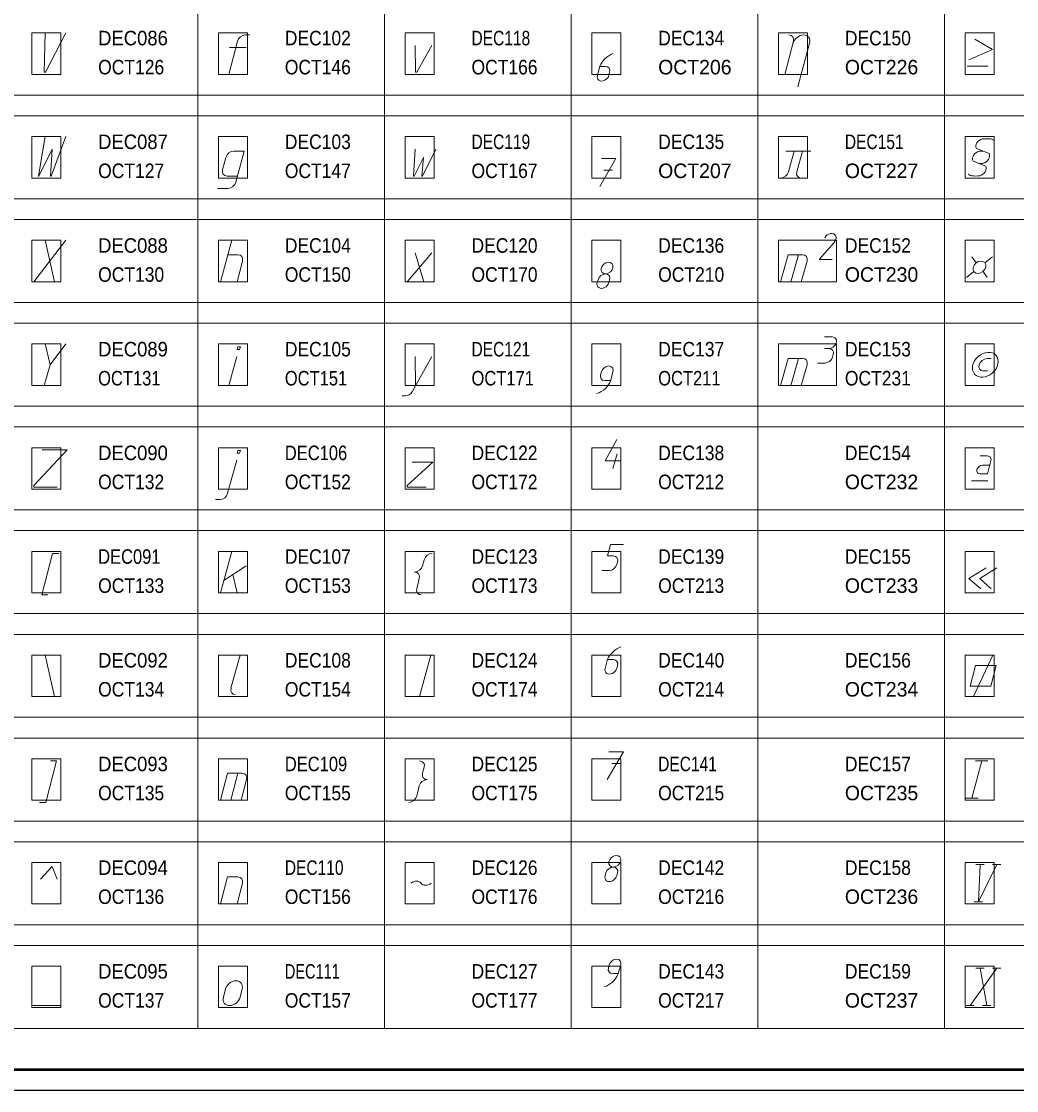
# Model space of a CAD drawing. Extents: x -200 to 7300, y -200 to 4800.
# Drawn here: x 2225 to 4624, y -200 to 2378 of the extents above; entities that cross this region are included whole.
import ezdxf

# ---------------------------------------------------------------- set-up
doc = ezdxf.new("R2010")
doc.units = 0
doc.header["$LTSCALE"] = 14
for name, color, linetype, lineweight in [('1', 7, 'Continuous', 13), ('5', 7, 'Continuous', 40), ('6', 7, 'Continuous', 13), ('63', 7, 'Continuous', 13)]:
    doc.layers.add(name, color=color, linetype=linetype, lineweight=lineweight)
doc.layers.add('10', color=7, linetype='Continuous')
doc.layers.add('11', color=7, linetype='Continuous')

msp = doc.modelspace()

# ---------------------------------------------------------------- linework, layer by layer
at = {"layer": '1'}
for p, q in [((2746, 2330), (2725, 2250)), ((2775, 2345), (2765, 2345)), ((4065, 2250), (4086, 2330)), ((4097, 2220), (4125, 2325)), ((2727, 2315), (2767, 2315)), ((3619, 2270), (3613.4, 2248)), ((3619, 2269), (3633, 2269)), ((4505, 2270), (4555, 2270)), ((3643, 2255), (3641.4, 2247.9)), ((4068, 2065), (4128, 2065)), ((4088, 2065), (4074, 2015)), ((4108, 2065), (4094, 2015)), ((4527, 2071), (4557.7, 2059)), ((2710, 2020), (2718, 2050)), ((4519, 2041), (4549.7, 2029)), ((3629, 2019), (3650, 2019)), ((2746, 2005), (2721, 2005)), ((2723, 1975), (2698, 1975)), ((2332, 1850), (2255, 1750)), ((2282, 1850), (2305, 1750)), ((2732, 1850), (2705, 1750)), ((2722, 1815), (2747, 1815)), ((3214, 1820), (3155, 1750)), ((3174, 1820), (3195, 1750)), ((4098, 1815), (4080, 1750)), ((4516, 1810), (4526.4, 1795.5)), ((4566, 1810), (4547.7, 1795.7)), ((2758, 1800), (2745, 1750)), ((4119, 1800), (4105, 1750)), ((3615, 1755), (3613, 1748)), ((3643, 1755), (3641, 1748)), ((4503, 1760), (4520.7, 1774.6)), ((4553, 1760), (4543, 1775)), ((4179, 1617), (4161, 1617)), ((4172, 1589), (4161, 1589)), ((4182, 1575), (4180, 1568)), ((2294, 1550), (2280, 1500)), ((2725, 1500), (2744, 1570)), ((3214, 1570), (3167, 1485)), ((3174, 1570), (3175, 1500)), ((4098, 1565), (4080, 1500)), ((4119, 1550), (4105, 1500)), ((4162, 1554), (4144, 1554)), ((4563, 1565), (4553, 1565)), ((3621, 1526), (3623, 1533)), ((3646, 1513), (3651, 1533)), ((4544, 1535), (4554, 1535)), ((3646, 1512), (3631, 1512)), ((3150, 1475), (3143, 1475)), ((2744, 1320), (2722, 1240)), ((3651, 1300), (3661, 1335)), ((4536, 1330), (4551.5, 1330)), ((4542, 1308), (4560, 1308)), ((4515, 1270), (4555, 1270)), ((2703, 1225), (2693, 1225)), ((2732, 1100), (2705, 1000)), ((2767, 1065), (2713, 1030)), ((3196, 1080), (3192, 1065)), ((3662, 1075), (3660, 1068)), ((2745, 1000), (2735, 1044)), ((3178, 1010), (3184, 1035)), ((3624, 1054), (3642, 1054)), ((2305, 750), (2282, 850)), ((2752, 850), (2730, 770)), ((3212, 850), (3185, 750)), ((3638, 840), (3632, 818)), ((3638, 839), (3652, 839)), ((3662, 825), (3660, 818)), ((4520, 750), (4567, 850)), ((4540, 595), (4516, 505)), ((4525, 595), (4555, 595)), ((3196, 580), (3192, 565)), ((3648, 589), (3669, 589)), ((2747, 565), (2730, 500)), ((2768, 550), (2755, 500)), ((3178, 510), (3184, 535)), ((4501, 505), (4531, 505)), ((4526, 345), (4546, 345)), ((4586, 345), (4566, 345)), ((3634, 325), (3632, 318)), ((3662, 325), (3660, 318)), ((2758, 300), (2745, 250)), ((4522, 255), (4542, 255)), ((3640, 96), (3642, 103)), ((3664, 82), (3650, 82)), ((3663, 80), (3670, 103)), ((4576, 95), (4512, 5)), ((4526, 95), (4546, 95)), ((4536, 95), (4552, 5)), ((4586, 95), (4566, 95)), ((2717, 45), (2712, 25)), ((2757, 45), (2752, 25)), ((2251, 5), (2321, 5)), ((4502, 5), (4522, 5)), ((4542, 5), (4562, 5))]:
    msp.add_line(p, q, dxfattribs=at)
for points in [[(2282, 2350), (2280, 2255), (2283, 2255), (2332, 2350)], [(3174, 2320), (3175, 2255), (3178, 2255), (3214, 2320)], [(4523, 2335), (4566, 2310), (4509, 2285)], [(2282, 2100), (2266, 2005), (2267, 2005), (2299, 2070), (2295, 2005), (2297, 2005), (2332, 2100)], [(2737, 2065), (2762, 2065), (2742, 1990)], [(3174, 2070), (3170, 2005), (3172, 2005), (3194, 2050), (3190, 2005), (3192, 2005), (3224, 2070)], [(3623, 2047), (3658, 2047), (3619, 1980)], [(4179, 1804), (4148, 1804), (4184, 1845)], [(4055, 1750), (4073, 1815), (4108, 1815)], [(2282, 1600), (2294, 1550), (2332, 1600)], [(4055, 1500), (4073, 1565), (4108, 1565)], [(3670, 1318), (3632, 1318), (3660, 1370)], [(2275, 1345), (2335, 1345), (2255, 1259), (2255, 1255), (2311, 1255)], [(3167, 1315), (3217, 1315), (3155, 1259), (3155, 1255), (3201, 1255)], [(4562, 1319), (4554, 1287), (4536, 1287)], [(3676, 1117), (3645, 1117), (3638, 1089), (3652, 1089)], [(2315, 1095), (2300, 1095), (2274, 995), (2289, 995)], [(4551, 1060), (4509, 1035), (4538, 1010)], [(4576, 1060), (4535, 1035), (4563, 1010)], [(2295, 595), (2310, 595), (2284, 495), (2269, 495)], [(3641, 617), (3676, 617), (3637, 550)], [(2705, 500), (2722, 565), (2757, 565)], [(2311, 310), (2299, 340), (2271, 310)], [(4536, 345), (4532, 255), (4576, 345)], [(2705, 250), (2722, 315), (2747, 315)]]:
    msp.add_lwpolyline(points, dxfattribs=at)
for points in [[(2745, 1587), (2751, 1587), (2753, 1593), (2747, 1593)], [(2745, 1337), (2751, 1337), (2753, 1343), (2747, 1343)], [(4512, 775), (4562, 775), (4575, 825), (4525, 825)]]:
    msp.add_lwpolyline(points, close=True, dxfattribs=at)
for centre, major_axis, ratio, start_param, end_param in [((2761, 2330), (-12.9, -11.29), 0.765566, 3.860429, 5.4312252), ((4071, 2330), (-12.9, -11.29), 0.765566, 2.2896327, 3.860429), ((4105, 2325), (-17.2, -15.05), 0.765566, 2.2896327, 5.4312253), ((3657.28, 2262.33), (-35.31, -30.9), 0.765566, 4.2695852, 5.2433836), ((3629, 2255), (-12.04, -10.54), 0.765566, 2.2896326, 3.8604289), ((3627.39, 2247.96), (-12.04, -10.54), 0.765566, 5.4286742, 8.5753689), ((4541.35, 2080), (-12.9, -11.29), 0.765566, 4.1387286, 6.0747263), ((4549.03, 2090), (-20.04, -0.36), 0.248806, 3.0702852, 5.1041698), ((2732.98, 2050), (-12.9, -11.29), 0.765566, 3.860429, 5.4312252), ((4533.32, 2050), (-12.9, -11.29), 0.765566, 4.1387286, 6.0747263), ((4541, 2060), (-20.04, -0.36), 0.248806, 4.6410815, 5.1041696), ((4543.32, 2050), (-12.9, -11.29), 0.765566, 0.9971359, 2.9331337), ((2725.02, 2020), (12.9, 11.29), 0.765566, 2.2896328, 3.860429), ((4058.98, 2014.85), (-12.94, -11.3), 0.762607, 0.7177368, 2.2885331), ((4108.97, 2014.85), (12.94, 11.3), 0.762607, 2.2885332, 3.8593294), ((4535.64, 2040), (-20.04, -0.36), 0.248806, 1.4994889, 2.0118784), ((4535.28, 2020), (-12.9, -11.29), 0.765566, 0.9971359, 2.9331337), ((2727.22, 1990), (-12.9, -11.29), 0.765566, 0.7188363, 2.2896326), ((4527.6, 2010), (-20.04, -0.36), 0.248806, 6.2118779, 8.2950638), ((4174.28, 1852.61), (-12.04, -10.54), 0.765566, 1.7153279, 5.1862467), ((2743, 1800), (-12.9, -11.29), 0.765566, 2.2896327, 3.860429), ((4104, 1800), (-12.94, -11.3), 0.762607, 2.2885331, 3.8593293), ((3629, 1755), (-12.04, -10.54), 0.765566, 2.2896326, 5.4312252), ((3627.01, 1748.04), (-12.04, -10.54), 0.765566, 5.4286742, 8.5753689), ((4175.55, 1602.98), (-12.06, -10.55), 0.765566, 0.646299, 3.8615683), ((4168.04, 1575), (-12.04, -10.54), 0.765566, 2.2896326, 3.8604289), ((3637, 1533), (-12.04, -10.54), 0.765566, 2.2896326, 5.4312252), ((4104, 1550), (-12.94, -11.3), 0.762607, 2.2885331, 3.8593293), ((4166, 1568), (12.04, 10.54), 0.765566, 3.860429, 5.4312252), ((4548.54, 1549.85), (12.94, 11.3), 0.762607, 2.2885332, 3.8593294), ((4548.54, 1549.85), (-12.94, -11.3), 0.762607, 3.8593293, 5.4301256), ((3635, 1526), (12.04, 10.54), 0.765566, 2.2896328, 3.860429), ((3608.34, 1516.83), (33.44, 29.26), 0.765566, 4.2103523, 5.3324913), ((3154.32, 1490), (12.9, 11.29), 0.765566, 3.8604291, 5.0573215), ((4551.13, 1319.29), (-9.22, -8.06), 0.796814, 2.2896327, 4.0681198), ((4539.13, 1297.29), (-9.22, -8.06), 0.765566, 3.860429, 7.0020216), ((2707.26, 1240), (-12.9, -11.29), 0.765566, 0.7188363, 2.2896326), ((3211, 1080), (-12.9, -11.29), 0.765566, 3.860429, 5.4312252), ((3648, 1075), (-12.04, -10.54), 0.765566, 2.2896326, 3.8604289), ((3177, 1065), (-12.9, -11.29), 0.765566, 0.7188363, 2.2896326), ((3646, 1068), (12.04, 10.54), 0.765566, 3.860429, 5.4312252), ((3169, 1035), (-12.9, -11.29), 0.765566, 2.2896327, 3.860429), ((3193, 1010), (12.9, 11.29), 0.765566, 2.2896328, 3.860429), ((3676.28, 832.33), (-35.31, -30.9), 0.765566, 4.2695852, 5.2433836), ((3648, 825), (-12.04, -10.54), 0.765566, 2.2896326, 3.8604289), ((3646.01, 818.04), (-12.04, -10.54), 0.765566, 5.4286742, 8.5753689), ((2745.33, 770), (12.9, 11.29), 0.765566, 2.2896327, 3.860429), ((3181, 580), (-12.9, -11.29), 0.765566, 2.2896328, 3.8604291), ((2753, 550), (-12.9, -11.29), 0.765566, 2.2896327, 3.860429), ((3198.98, 535), (-12.9, -11.29), 0.765566, 3.8604291, 5.4312254), ((3207, 565), (12.9, 11.29), 0.765566, 2.2896328, 3.860429), ((3163, 510), (-12.9, -11.29), 0.765566, 0.7188363, 2.2896326), ((3648, 325), (-12.04, -10.54), 0.765566, 2.2896326, 5.4312252), ((2742.98, 300), (-12.9, -11.29), 0.765566, 2.2896327, 3.860429), ((3646.01, 318.04), (-12.04, -10.54), 0.765566, 5.4286742, 8.5753689), ((3173.19, 288), (-14.6, -12.77), 0.765566, 3.0750308, 4.6457939), ((3203.63, 312), (-14.6, -12.77), 0.765566, 6.2166235, 7.7873867), ((3656, 103), (-12.04, -10.54), 0.765566, 2.2896326, 5.4312252), ((3626.42, 86.52), (33.44, 29.26), 0.765566, 4.2103523, 5.2626218), ((3654, 96), (12.04, 10.54), 0.765566, 2.2896328, 3.860429), ((2737, 45), (-17.2, -15.05), 0.765566, 2.2896326, 5.4312252), ((2732, 25), (17.2, 15.05), 0.765566, 2.2896328, 5.4312254)]:
    msp.add_ellipse(centre, major_axis=major_axis, ratio=ratio, start_param=start_param, end_param=end_param, dxfattribs=at)
for centre, major_axis, ratio in [((3636.81, 1783), (-12.04, -10.54), 0.765566), ((4534.31, 1785), (-12.9, -11.29), 0.765566), ((4548.54, 1549.85), (-25.87, -22.6), 0.762607), ((3655.4, 353), (-12.04, -10.54), 0.765566)]:
    msp.add_ellipse(centre, major_axis=major_axis, ratio=ratio, dxfattribs=at)
at = {"layer": '5', "lineweight": 53}
msp.add_line((7150, -150), (-50, -150), dxfattribs=at)
at = {"layer": '5', "lineweight": 25}
msp.add_lwpolyline([(-200, -200), (-200, 4800), (7300, 4800), (7300, -200)], close=True, dxfattribs=at)
at = {"layer": '6'}
for p, q in [((2650, 3950), (2650, -50)), ((3100, 3950), (3100, -50)), ((3550, 3950), (3550, -50)), ((4000, 3950), (4000, -50)), ((4450, 3950), (4450, -50)), ((-50, 2200), (7150, 2200)), ((-50, 2150), (7150, 2150)), ((-50, 1950), (7150, 1950)), ((-50, 1900), (7150, 1900)), ((-50, 1700), (7150, 1700)), ((-50, 1650), (7150, 1650)), ((-50, 1450), (7150, 1450)), ((-50, 1400), (7150, 1400)), ((-50, 1200), (7150, 1200)), ((-50, 1150), (7150, 1150)), ((-50, 950), (7150, 950)), ((-50, 900), (7150, 900)), ((-50, 700), (7150, 700)), ((-50, 650), (7150, 650)), ((-50, 450), (7150, 450)), ((-50, 400), (7150, 400)), ((-50, 200), (7150, 200)), ((-50, 150), (7150, 150)), ((-50, -50), (7150, -50))]:
    msp.add_line(p, q, dxfattribs=at)
at = {"layer": '63'}
for points in [[(2250, 2250), (2320, 2250), (2320, 2350), (2250, 2350)], [(2700, 2250), (2770, 2250), (2770, 2350), (2700, 2350)], [(3150, 2250), (3220, 2250), (3220, 2350), (3150, 2350)], [(3600, 2250), (3670, 2250), (3670, 2350), (3600, 2350)], [(4050, 2250), (4120, 2250), (4120, 2350), (4050, 2350)], [(4500, 2250), (4570, 2250), (4570, 2350), (4500, 2350)], [(2250, 2000), (2320, 2000), (2320, 2100), (2250, 2100)], [(2700, 2000), (2770, 2000), (2770, 2100), (2700, 2100)], [(3150, 2000), (3220, 2000), (3220, 2100), (3150, 2100)], [(3600, 2000), (3670, 2000), (3670, 2100), (3600, 2100)], [(4050, 2000), (4120, 2000), (4120, 2100), (4050, 2100)], [(4500, 2000), (4570, 2000), (4570, 2100), (4500, 2100)], [(2250, 1750), (2320, 1750), (2320, 1850), (2250, 1850)], [(2700, 1750), (2770, 1750), (2770, 1850), (2700, 1850)], [(3150, 1750), (3220, 1750), (3220, 1850), (3150, 1850)], [(3600, 1750), (3670, 1750), (3670, 1850), (3600, 1850)], [(4050, 1750), (4190, 1750), (4190, 1850), (4050, 1850)], [(4500, 1750), (4570, 1750), (4570, 1850), (4500, 1850)], [(2250, 1500), (2320, 1500), (2320, 1600), (2250, 1600)], [(2700, 1500), (2770, 1500), (2770, 1600), (2700, 1600)], [(3150, 1500), (3220, 1500), (3220, 1600), (3150, 1600)], [(3600, 1500), (3670, 1500), (3670, 1600), (3600, 1600)], [(4050, 1500), (4190, 1500), (4190, 1600), (4050, 1600)], [(4500, 1500), (4570, 1500), (4570, 1600), (4500, 1600)], [(2250, 1250), (2320, 1250), (2320, 1350), (2250, 1350)], [(2700, 1250), (2770, 1250), (2770, 1350), (2700, 1350)], [(3150, 1250), (3220, 1250), (3220, 1350), (3150, 1350)], [(3600, 1250), (3670, 1250), (3670, 1350), (3600, 1350)], [(4500, 1250), (4570, 1250), (4570, 1350), (4500, 1350)], [(2250, 1000), (2320, 1000), (2320, 1100), (2250, 1100)], [(2700, 1000), (2770, 1000), (2770, 1100), (2700, 1100)], [(3150, 1000), (3220, 1000), (3220, 1100), (3150, 1100)], [(3600, 1000), (3670, 1000), (3670, 1100), (3600, 1100)], [(4500, 1000), (4570, 1000), (4570, 1100), (4500, 1100)], [(2250, 750), (2320, 750), (2320, 850), (2250, 850)], [(2700, 750), (2770, 750), (2770, 850), (2700, 850)], [(3150, 750), (3220, 750), (3220, 850), (3150, 850)], [(3600, 750), (3670, 750), (3670, 850), (3600, 850)], [(4500, 750), (4570, 750), (4570, 850), (4500, 850)], [(2250, 500), (2320, 500), (2320, 600), (2250, 600)], [(2700, 500), (2770, 500), (2770, 600), (2700, 600)], [(3150, 500), (3220, 500), (3220, 600), (3150, 600)], [(3600, 500), (3670, 500), (3670, 600), (3600, 600)], [(4500, 500), (4570, 500), (4570, 600), (4500, 600)], [(2250, 250), (2320, 250), (2320, 350), (2250, 350)], [(2700, 250), (2770, 250), (2770, 350), (2700, 350)], [(3150, 250), (3220, 250), (3220, 350), (3150, 350)], [(3600, 250), (3670, 250), (3670, 350), (3600, 350)], [(4500, 250), (4570, 250), (4570, 350), (4500, 350)], [(2250, 0), (2320, 0), (2320, 100), (2250, 100)], [(2700, 0), (2770, 0), (2770, 100), (2700, 100)], [(3600, 0), (3670, 0), (3670, 100), (3600, 100)], [(4500, 0), (4570, 0), (4570, 100), (4500, 100)]]:
    msp.add_lwpolyline(points, close=True, dxfattribs=at)

# ---------------------------------------------------------------- texts
at = {"layer": '10'}
for s, width, p in [('DEC086', 0.95, (2410, 2320)), ('DEC102', 0.9, (2860, 2320)), ('DEC118', 0.8, (3310, 2320)), ('DEC134', 0.9, (3760, 2320)), ('DEC150', 0.9, (4210, 2320)), ('DEC087', 0.95, (2410, 2070)), ('DEC103', 0.9, (2860, 2070)), ('DEC119', 0.8, (3310, 2070)), ('DEC135', 0.9, (3760, 2070)), ('DEC151', 0.8, (4210, 2070)), ('DEC088', 0.95, (2410, 1820)), ('DEC104', 0.9, (2860, 1820)), ('DEC120', 0.9, (3310, 1820)), ('DEC136', 0.9, (3760, 1820)), ('DEC152', 0.9, (4210, 1820)), ('DEC089', 0.95, (2410, 1570)), ('DEC105', 0.9, (2860, 1570)), ('DEC121', 0.8, (3310, 1570)), ('DEC137', 0.9, (3760, 1570)), ('DEC153', 0.9, (4210, 1570)), ('DEC090', 0.95, (2410, 1320)), ('DEC106', 0.85, (2860, 1320)), ('DEC122', 0.9, (3310, 1320)), ('DEC138', 0.9, (3760, 1320)), ('DEC154', 0.9, (4210, 1320)), ('DEC091', 0.85, (2410, 1070)), ('DEC107', 0.9, (2860, 1070)), ('DEC123', 0.9, (3310, 1070)), ('DEC139', 0.9, (3760, 1070)), ('DEC155', 0.9, (4210, 1070)), ('DEC092', 0.95, (2410, 820)), ('DEC108', 0.9, (2860, 820)), ('DEC124', 0.9, (3310, 820)), ('DEC140', 0.9, (3760, 820)), ('DEC156', 0.9, (4210, 820)), ('DEC093', 0.95, (2410, 570)), ('DEC109', 0.85, (2860, 570)), ('DEC125', 0.9, (3310, 570)), ('DEC141', 0.8, (3760, 570)), ('DEC157', 0.9, (4210, 570)), ('DEC094', 0.95, (2410, 320)), ('DEC110', 0.8, (2860, 320)), ('DEC126', 0.9, (3310, 320)), ('DEC142', 0.9, (3760, 320)), ('DEC158', 0.9, (4210, 320)), ('DEC095', 0.95, (2410, 70)), ('DEC111', 0.75, (2860, 70)), ('DEC127', 0.9, (3310, 70)), ('DEC143', 0.9, (3760, 70)), ('DEC159', 0.9, (4210, 70))]:
    msp.add_text(s, height=35, dxfattribs=dict(at, width=width)).set_placement(p)
at = {"layer": '11'}
for s, width, p in [('OCT126', 0.9, (2410, 2250)), ('OCT146', 0.9, (2860, 2250)), ('OCT166', 0.9, (3310, 2250)), ('OCT127', 0.9, (2410, 2000)), ('OCT147', 0.9, (2860, 2000)), ('OCT167', 0.9, (3310, 2000)), ('OCT130', 0.9, (2410, 1750)), ('OCT150', 0.9, (2860, 1750)), ('OCT170', 0.9, (3310, 1750)), ('OCT210', 0.9, (3760, 1750)), ('OCT131', 0.85, (2410, 1500)), ('OCT151', 0.85, (2860, 1500)), ('OCT171', 0.85, (3310, 1500)), ('OCT211', 0.85, (3760, 1500)), ('OCT231', 0.9, (4210, 1500)), ('OCT132', 0.9, (2410, 1250)), ('OCT152', 0.9, (2860, 1250)), ('OCT172', 0.9, (3310, 1250)), ('OCT212', 0.9, (3760, 1250)), ('OCT133', 0.9, (2410, 1000)), ('OCT153', 0.9, (2860, 1000)), ('OCT173', 0.9, (3310, 1000)), ('OCT213', 0.9, (3760, 1000)), ('OCT134', 0.9, (2410, 750)), ('OCT154', 0.9, (2860, 750)), ('OCT174', 0.9, (3310, 750)), ('OCT214', 0.9, (3760, 750)), ('OCT135', 0.9, (2410, 500)), ('OCT155', 0.9, (2860, 500)), ('OCT175', 0.9, (3310, 500)), ('OCT215', 0.9, (3760, 500)), ('OCT136', 0.9, (2410, 250)), ('OCT156', 0.9, (2860, 250)), ('OCT176', 0.9, (3310, 250)), ('OCT216', 0.9, (3760, 250)), ('OCT137', 0.9, (2410, 0)), ('OCT157', 0.9, (2860, 0)), ('OCT177', 0.9, (3310, 0)), ('OCT217', 0.9, (3760, 0))]:
    msp.add_text(s, height=35, dxfattribs=dict(at, width=width)).set_placement(p)
for s, p in [('OCT206', (3760, 2250)), ('OCT226', (4210, 2250)), ('OCT207', (3760, 2000)), ('OCT227', (4210, 2000)), ('OCT230', (4210, 1750)), ('OCT232', (4210, 1250)), ('OCT233', (4210, 1000)), ('OCT234', (4210, 750)), ('OCT235', (4210, 500)), ('OCT236', (4210, 250)), ('OCT237', (4210, 0))]:
    msp.add_text(s, height=35, dxfattribs=at).set_placement(p)

doc.saveas('drawing.dxf')
